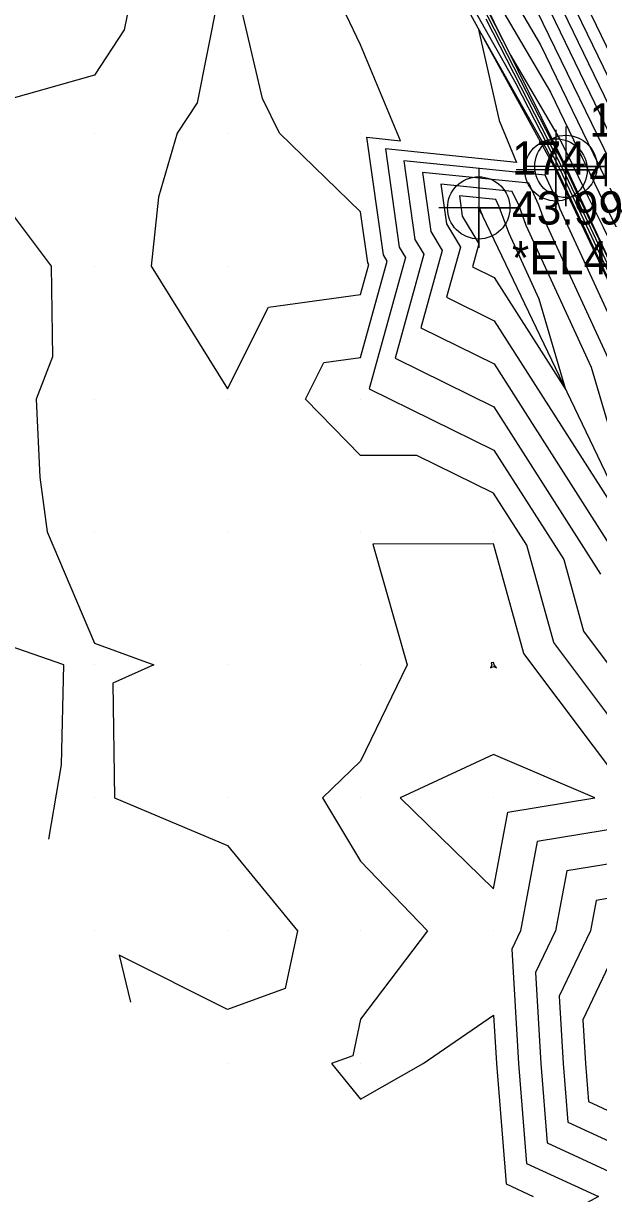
# Model space of a CAD drawing. Extents: x 2090860 to 2091277, y 159470 to 160080.
# Drawn here: x 2091044.6 to 2091087.9, y 159590.2 to 159678.3 of the extents above; entities that cross this region are included whole.
import ezdxf

# ---------------------------------------------------------------- set-up
doc = ezdxf.new("R2010")
doc.units = 0
for name, color, linetype in [('DTM Contours Major', 7, 'Continuous'), ('DTM Contours Minor', 7, 'Continuous'), ('Exist DTM Breakline', 7, 'Continuous'), ('Exist DTM Breakline Cogo Comment', 7, 'Continuous'), ('Exist DTM Breakline Cogo Elevation', 7, 'Continuous'), ('Exist DTM Breakline Cogo Number', 7, 'Continuous'), ('Exist DTM Breakline Cogo Point CELL', 7, 'Continuous'), ('Exist DTM QL2 LIDAR Elevation Point', 7, 'Continuous')]:
    doc.layers.add(name, color=color, linetype=linetype)

msp = doc.modelspace()

# ---------------------------------------------------------------- linework, layer by layer
at = {"layer": 'DTM Contours Major'}
for points in [[(2091079.813, 159694.479), (2091091.479, 159670.351), (2091092.674, 159667.942), (2091092.718, 159667.852), (2091101.365, 159650.434), (2091105.185, 159642.793), (2091106.067, 159640.964), (2091111.338, 159629.685), (2091111.718, 159628.889), (2091112.961, 159626.284), (2091124.433, 159601.716), (2091124.607, 159601.347), (2091126.942, 159596.528), (2091128.343, 159593.558), (2091139.93, 159569.539)], [(2091077.176, 159683.472), (2091085.357, 159667.475), (2091085.495, 159667.182), (2091086.555, 159664.923), (2091087.913, 159662.036), (2091093.577, 159649.962), (2091099.498, 159637.849), (2091099.709, 159637.399), (2091104.938, 159625.32), (2091105.136, 159624.896), (2091108.736, 159616.547), (2091117.028, 159597.858), (2091117.244, 159597.435), (2091119.625, 159592.62), (2091130.861, 159569.9)], [(2091082.79, 159680.214), (2091088.287, 159668.846), (2091088.85, 159667.711), (2091089.525, 159666.328), (2091095.999, 159653.287), (2091102.781, 159639.414), (2091105.76, 159633.037), (2091108.329, 159627.103), (2091114.857, 159613.131), (2091120.634, 159599.73), (2091121.876, 159597.167), (2091123.209, 159594.519), (2091129.912, 159580.676)], [(2091095.262, 159642.075), (2091085.023, 159664.299), (2091084.888, 159664.67), (2091083.884, 159666.846), (2091073.261, 159667.939), (2091074.092, 159662.019), (2091074.755, 159660.906), (2091072.594, 159653.071), (2091080.029, 159649.409), (2091088.053, 159636.828)], [(2091079.163, 159663.808), (2091078.951, 159664.388), (2091078.94, 159664.412), (2091078.825, 159664.424), (2091078.834, 159664.359), (2091079.163, 159663.808)], [(2091080.042, 159630.016), (2091080, 159630.168), (2091079.833, 159630.167), (2091079.88, 159630), (2091079.768, 159629.768), (2091080, 159629.875), (2091080.217, 159629.783), (2091080.042, 159630.016)], [(2091110.007, 159579.993), (2091110.002, 159580.004), (2091103.432, 159589.881), (2091102.785, 159591.228), (2091101.952, 159599.105), (2091099.755, 159604.353), (2091092.873, 159614.018), (2091090, 159617.816), (2091083.295, 159616.705), (2091082.036, 159610), (2091081.379, 159608.621), (2091081.89, 159600), (2091082.493, 159592.493), (2091087.89, 159590), (2091082.789, 159587.211), (2091083.053, 159580), (2091090, 159570.963), (2091096.054, 159573.946), (2091100, 159579.609), (2091100.406, 159579.594), (2091110, 159579.988), (2091110.007, 159579.993)]]:
    msp.add_lwpolyline(points, dxfattribs=at)
at = {"layer": 'DTM Contours Minor'}
for points in [[(2091072.913, 159694.755), (2091083.535, 159676.648), (2091087.489, 159668.47), (2091087.894, 159667.653), (2091088.727, 159665.947), (2091093.416, 159656.501), (2091101.96, 159639.023), (2091104.247, 159634.128), (2091107.481, 159626.657), (2091112.427, 159616.072), (2091119.685, 159599.236), (2091120.595, 159597.359), (2091122.273, 159594.024), (2091127.204, 159583.841)], [(2091070.474, 159693.642), (2091081.681, 159673.757), (2091084.964, 159667.339), (2091085.735, 159665.698), (2091086.157, 159664.799), (2091094.809, 159646.403), (2091098.918, 159637.644), (2091102.338, 159629.862), (2091104.449, 159625.11), (2091112.732, 159606.254), (2091116.546, 159597.659), (2091118.37, 159594.073), (2091119.204, 159592.386), (2091123.926, 159582.838)], [(2091073.926, 159690.732), (2091084.279, 159673.082), (2091086.691, 159668.093), (2091086.938, 159667.595), (2091087.929, 159665.566), (2091090.833, 159659.715), (2091101.14, 159638.632), (2091102.735, 159635.218), (2091106.633, 159626.212), (2091109.996, 159619.013), (2091118.736, 159598.741), (2091119.313, 159597.552), (2091121.338, 159593.528), (2091124.496, 159587.006)], [(2091080.558, 159690.913), (2091090.681, 159669.974), (2091091.718, 159667.884), (2091091.92, 159667.471), (2091103.748, 159643.645), (2091105.242, 159640.588), (2091110.299, 159629.767), (2091110.873, 159628.44), (2091122.148, 159604.306), (2091123.481, 159601.214), (2091125.721, 159596.589), (2091126.015, 159596.005), (2091138.036, 159571.181)], [(2091074.923, 159688.329), (2091081.29, 159675.881), (2091085.023, 159669.516), (2091085.893, 159667.717), (2091085.982, 159667.538), (2091087.13, 159665.185), (2091088.251, 159662.929), (2091100.319, 159638.24), (2091101.222, 159636.308), (2091105.785, 159625.766), (2091107.566, 159621.955), (2091117.788, 159598.247), (2091118.031, 159597.744), (2091120.402, 159593.033), (2091121.788, 159590.171)], [(2091081.302, 159687.347), (2091089.883, 159669.598), (2091090.762, 159667.827), (2091091.122, 159667.09), (2091101.165, 159646.859), (2091104.422, 159640.197), (2091108.786, 159630.857), (2091110.025, 159627.994), (2091119.717, 159607.248), (2091122.532, 159600.719), (2091124.44, 159596.782), (2091125.08, 159595.509), (2091135.328, 159574.346)], [(2091082.046, 159683.781), (2091089.085, 159669.222), (2091089.806, 159667.769), (2091090.323, 159666.709), (2091098.582, 159650.073), (2091103.601, 159639.806), (2091107.273, 159631.947), (2091109.177, 159627.548), (2091117.287, 159610.189), (2091121.583, 159600.225), (2091123.158, 159596.974), (2091124.144, 159595.014), (2091132.62, 159577.511)], [(2091070.535, 159660.264), (2091070, 159664.078), (2091063.899, 159670), (2091062.629, 159672.629), (2091060.888, 159680), (2091060, 159680.513), (2091059.079, 159680.921), (2091059.246, 159680), (2091057.702, 159672.298), (2091056.213, 159670), (2091054.811, 159665.189), (2091054.242, 159660), (2091060, 159650.781), (2091063.085, 159656.915), (2091070, 159657.864), (2091070.622, 159660.118), (2091070.535, 159660.264)], [(2091052.659, 159680), (2091052.215, 159677.785), (2091050, 159674.366), (2091042.178, 159672.178)], [(2091106.329, 159589.78), (2091105.135, 159592.265), (2091104.537, 159597.919), (2091099.429, 159610.12), (2091094.767, 159616.667), (2091091.883, 159620.481), (2091090.706, 159623.465), (2091084.527, 159631.691), (2091082.5, 159639.015), (2091080.009, 159642.921), (2091074.236, 159645.764), (2091070, 159645.752), (2091065.862, 159650), (2091067.247, 159652.753), (2091070, 159653.131), (2091071.999, 159660.381), (2091071.72, 159660.849), (2091070.48, 159669.697), (2091073.008, 159669.437), (2091070, 159676.646), (2091068.908, 159678.908)], [(2091079.429, 159678.614), (2091085.16, 159667.407), (2091085.615, 159666.44), (2091086.356, 159664.861), (2091091.361, 159654.219), (2091099.113, 159637.695), (2091100.516, 159634.501), (2091104.653, 159625.193), (2091108.518, 159616.394), (2091116.787, 159597.759), (2091117.807, 159595.754), (2091119.414, 159592.503), (2091128.512, 159574.108)], [(2091098.257, 159638.587), (2091085.958, 159664.737), (2091085.856, 159664.956), (2091084.767, 159667.271), (2091083.934, 159668.899), (2091078.855, 159677.911), (2091080.414, 159670.966), (2091081.733, 159667.803), (2091071.87, 159668.818), (2091072.906, 159661.434), (2091073.377, 159660.644), (2091070.656, 159650.776), (2091080.019, 159646.165), (2091085.277, 159637.922), (2091086.769, 159632.529), (2091091.319, 159626.472)], [(2091040, 159668.921), (2091046.718, 159660), (2091046.828, 159653.172), (2091045.596, 159650), (2091045.866, 159644.134), (2091046.438, 159640), (2091050, 159631.644), (2091054.46, 159630), (2091051.375, 159628.625), (2091051.492, 159620), (2091060, 159616.418), (2091065.256, 159610), (2091064.339, 159605.661), (2091060, 159604.081), (2091051.839, 159608.161), (2091052.695, 159604.61)], [(2091091.322, 159647.221), (2091083.738, 159663.682), (2091083.404, 159664.599), (2091082.648, 159666.238), (2091074.652, 159667.06), (2091075.277, 159662.604), (2091076.133, 159661.169), (2091074.532, 159655.366), (2091080.039, 159652.653), (2091090.83, 159635.734)], [(2091081.412, 159665.629), (2091076.043, 159666.181), (2091076.463, 159663.189), (2091077.511, 159661.431), (2091076.47, 159657.66), (2091080.049, 159655.898), (2091091.723, 159637.594), (2091087.381, 159652.367), (2091082.453, 159663.064), (2091081.92, 159664.529), (2091081.412, 159665.629)], [(2091080.176, 159665.02), (2091077.434, 159665.303), (2091077.648, 159663.774), (2091078.888, 159661.694), (2091078.409, 159659.955), (2091080.059, 159659.142), (2091085.443, 159650.7), (2091083.441, 159657.513), (2091081.168, 159662.447), (2091080.435, 159664.459), (2091080.176, 159665.02)], [(2091046.552, 159616.895), (2091047.512, 159622.488), (2091047.686, 159630), (2091040, 159632.655), (2091033.409, 159646.591), (2091033.971, 159650), (2091030, 159652.382), (2091028.851, 159651.5), (2091038.778, 159631.877)], [(2091104.88, 159589.83), (2091103.96, 159591.747), (2091103.244, 159598.512), (2091099.592, 159607.237), (2091093.82, 159615.342), (2091090.249, 159620.064), (2091090.093, 159620.458), (2091082.284, 159630.854), (2091080, 159639.109), (2091070.926, 159639.074), (2091073.494, 159630), (2091070, 159622.762), (2091067.148, 159620), (2091070, 159615.229), (2091075.044, 159610), (2091070, 159603.341), (2091069.417, 159600.583), (2091067.816, 159600), (2091070, 159597.318), (2091074.705, 159600), (2091080, 159603.65), (2091080.216, 159600), (2091080.944, 159590.944), (2091082.987, 159590)], [(2091087.629, 159620), (2091080, 159623.249), (2091072.986, 159620), (2091080, 159613.143), (2091081.084, 159618.916), (2091087.629, 159620)], [(2091101.984, 159589.931), (2091101.609, 159590.71), (2091100.659, 159599.698), (2091099.917, 159601.47), (2091091.925, 159612.693), (2091090, 159615.239), (2091085.506, 159614.494), (2091084.662, 159610), (2091083.158, 159606.842), (2091083.563, 159600), (2091084.042, 159594.042), (2091090, 159591.29), (2091095.276, 159595.276), (2091092.937, 159590), (2091100, 159583.938), (2091105.788, 159584.212), (2091101.984, 159589.931)], [(2091090.978, 159611.368), (2091090, 159612.662), (2091087.717, 159612.283), (2091087.288, 159610), (2091084.937, 159605.063), (2091085.237, 159600), (2091085.591, 159595.591), (2091090, 159593.555), (2091098.531, 159600), (2091096.782, 159603.218), (2091090.978, 159611.368)], [(2091090.031, 159610.043), (2091090, 159610.085), (2091089.927, 159610.073), (2091089.914, 159610), (2091086.716, 159603.284), (2091086.911, 159600), (2091087.14, 159597.14), (2091090, 159595.819), (2091095.534, 159600), (2091090.215, 159609.785), (2091090.031, 159610.043)]]:
    msp.add_lwpolyline(points, dxfattribs=at)
at = {"layer": 'Exist DTM Breakline'}
for points in [[(2091169.184, 159489.682), (2091149.135, 159531.027), (2091132.914, 159565.727), (2091117.093, 159597.885), (2091099.249, 159637.73), (2091085.443, 159667.505), (2091069.301, 159700.059), (2091060.276, 159722.819), (2091058.458, 159734.195), (2091059.361, 159735), (2091060.617, 159735.809)], [(2091168.326, 159489.347), (2091148.612, 159530.829), (2091132.315, 159565.389), (2091116.339, 159597.574), (2091098.698, 159637.587), (2091084.7, 159667.248), (2091067.163, 159699.242), (2091053.414, 159724.442), (2091052.893, 159730.303), (2091057.39, 159734.945)], [(2091163.514, 159486.332), (2091143.762, 159527.932), (2091127.118, 159562.647), (2091111.114, 159594.902), (2091093.029, 159634.868), (2091078.886, 159664.385)]]:
    msp.add_lwpolyline(points, dxfattribs=at)
at = {"layer": 'Exist DTM Breakline Cogo Point CELL'}
for points in [[(2091084.7, 159670.248), (2091084.7, 159664.248), (2091084.7, 159667.248), (2091087.7, 159667.248), (2091081.7, 159667.248)], [(2091085.443, 159670.505), (2091085.443, 159664.505), (2091085.443, 159667.505), (2091088.443, 159667.505), (2091082.443, 159667.505)], [(2091078.886, 159667.385), (2091078.886, 159661.385), (2091078.886, 159664.385), (2091081.886, 159664.385), (2091075.886, 159664.385)]]:
    msp.add_lwpolyline(points, dxfattribs=at)
for centre in [(2091084.7, 159667.248), (2091085.443, 159667.505), (2091078.886, 159664.385)]:
    msp.add_circle(centre, 2.344, dxfattribs=at)
at = {"layer": 'Exist DTM QL2 LIDAR Elevation Point'}
for p, q in [((2091050, 159670), (2091050, 159670)), ((2091060, 159670), (2091060, 159670)), ((2091070, 159670), (2091070, 159670)), ((2091050, 159660), (2091050, 159660)), ((2091060, 159660), (2091060, 159660)), ((2091070, 159660), (2091070, 159660)), ((2091050, 159650), (2091050, 159650)), ((2091060, 159650), (2091060, 159650)), ((2091070, 159650), (2091070, 159650)), ((2091050, 159640), (2091050, 159640)), ((2091060, 159640), (2091060, 159640)), ((2091070, 159640), (2091070, 159640)), ((2091080, 159640), (2091080, 159640)), ((2091050, 159630), (2091050, 159630)), ((2091060, 159630), (2091060, 159630)), ((2091070, 159630), (2091070, 159630)), ((2091080, 159630), (2091080, 159630)), ((2091050, 159620), (2091050, 159620)), ((2091060, 159620), (2091060, 159620)), ((2091070, 159620), (2091070, 159620)), ((2091080, 159620), (2091080, 159620)), ((2091050, 159610), (2091050, 159610)), ((2091060, 159610), (2091060, 159610)), ((2091070, 159610), (2091070, 159610)), ((2091080, 159610), (2091080, 159610)), ((2091060, 159600), (2091060, 159600)), ((2091070, 159600), (2091070, 159600)), ((2091080, 159600), (2091080, 159600))]:
    msp.add_line(p, q, dxfattribs=at)

# ---------------------------------------------------------------- texts
at = {"layer": 'Exist DTM Breakline Cogo Comment'}
msp.add_text('*EL40058', height=2.5, dxfattribs=at).set_placement((2091081.386, 159659.385))
at = {"layer": 'Exist DTM Breakline Cogo Elevation'}
for s, p in [('45.16', (2091087.2, 159665.998)), ('43.99', (2091081.386, 159663.135))]:
    msp.add_text(s, height=2.5, dxfattribs=at).set_placement(p)
at = {"layer": 'Exist DTM Breakline Cogo Number'}
for s, p in [('175', (2091087.2, 159669.748)), ('174', (2091081.386, 159666.885))]:
    msp.add_text(s, height=2.5, dxfattribs=at).set_placement(p)

doc.saveas('drawing.dxf')
